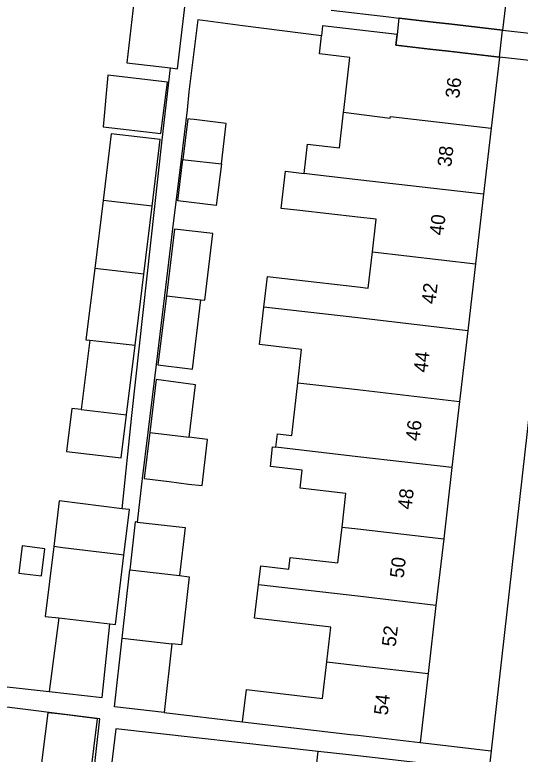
# Model space of a CAD drawing. Extents: x 161696 to 162377, y 380761 to 381673.
# Drawn here: x 161975.5 to 162011.6, y 381041 to 381093.8 of the extents above; entities that cross this region are included whole.
import ezdxf

# ---------------------------------------------------------------- set-up
doc = ezdxf.new("R2010")
doc.units = 0
for name, color, linetype in [('IMGEO_Pand', 7, 'Continuous'), ('IMGEO_Pand_nummerreeks', 7, 'Continuous'), ('IMGEO_Pand_overbouw', 7, 'Continuous'), ('IMGEO_Voetpad_open', 7, 'Continuous')]:
    doc.layers.add(name, color=color, linetype=linetype)

msp = doc.modelspace()

# ---------------------------------------------------------------- linework, layer by layer
at = {"layer": 'IMGEO_Pand'}
for points in [[(162010.992, 381098.263), (162010.343, 381092.663)], [(161984.096, 381095.314), (161983.519, 381090.325), (161986.632, 381089.965)], [(161986.632, 381089.965), (161987.14, 381089.906), (161987.745, 381095.141), (161984.124, 381095.56), (161984.096, 381095.314)], [(161998.101, 381094.083), (162002.22, 381093.605), (162002.942, 381093.521), (162002.961, 381093.519), (162005.377, 381093.239), (162006.726, 381093.082), (162010.343, 381092.663)], [(162010.119, 381090.735), (162006.477, 381091.157), (162005.153, 381091.311), (162002.718, 381091.593), (162002.806, 381092.348), (161997.491, 381092.965), (161997.41, 381092.267)], [(161998.983, 381086.811), (161998.997, 381086.93), (161999.437, 381090.719), (161997.26, 381090.972), (161997.41, 381092.267)], [(162010.119, 381090.735), (162009.531, 381085.664)], [(161985.946, 381085.299), (161986.41, 381088.96), (161982.155, 381089.452), (161981.82, 381085.776), (161985.946, 381085.299)], [(161996.182, 381082.433), (161996.424, 381084.519), (161998.686, 381084.256), (161998.983, 381086.811)], [(161998.983, 381086.811), (162002.315, 381086.376), (162002.329, 381086.499), (162009.531, 381085.664)], [(161990.265, 381083.119), (161990.616, 381086.009), (161988.331, 381086.287), (161988.028, 381086.324), (161987.876, 381086.342), (161987.522, 381083.437)], [(162009.531, 381085.664), (162008.985, 381080.948)], [(161985.322, 381080.096), (161985.906, 381084.854), (161982.4, 381085.259), (161981.816, 381080.502)], [(161990.265, 381083.119), (161989.902, 381080.141), (161987.161, 381080.475), (161987.522, 381083.437)], [(161987.522, 381083.437), (161987.676, 381083.419), (161990.265, 381083.119)], [(162001.043, 381076.835), (162001.314, 381079.187), (162000, 381079.311), (161995.875, 381079.789), (161994.524, 381079.946), (161994.831, 381082.59), (161996.182, 381082.433)], [(162008.985, 381080.948), (162000, 381081.99), (161996.945, 381082.344), (161996.182, 381082.433)], [(162008.985, 381080.948), (162008.409, 381075.981)], [(161981.816, 381080.502), (161981.22, 381075.647)], [(161985.322, 381080.096), (161981.816, 381080.502)], [(161984.728, 381075.257), (161985.322, 381080.096)], [(161988.801, 381073.427), (161989.082, 381073.394), (161989.661, 381078.154), (161986.917, 381078.473), (161986.337, 381073.713)], [(161993.302, 381072.906), (161993.555, 381075.087), (161995.419, 381074.871), (162000, 381074.34), (162000.746, 381074.253), (162001.043, 381076.835)], [(162001.043, 381076.835), (162008.409, 381075.981)], [(161981.22, 381075.647), (161980.596, 381070.56), (161980.873, 381070.529)], [(161984.728, 381075.257), (161981.22, 381075.647)], [(162008.409, 381075.981), (162007.857, 381071.218)], [(161984.104, 381070.174), (161984.728, 381075.257)], [(161986.337, 381073.713), (161985.737, 381068.79), (161988.027, 381068.491), (161988.197, 381068.469), (161988.801, 381073.427)], [(161986.337, 381073.713), (161988.801, 381073.427)], [(161995.72, 381067.506), (161995.995, 381069.879), (161992.992, 381070.227), (161993.302, 381072.906)], [(162007.857, 381071.218), (162000, 381072.129), (161995.166, 381072.69), (161993.302, 381072.906)], [(162007.857, 381071.218), (162007.271, 381066.168)], [(161980.873, 381070.529), (161980.267, 381065.59)], [(161980.873, 381070.529), (161984.104, 381070.174)], [(161983.496, 381065.217), (161984.104, 381070.174)], [(161987.966, 381063.615), (161988.422, 381067.361), (161985.608, 381067.728), (161985.146, 381063.942)], [(161994.163, 381062.898), (161994.273, 381063.848), (161995.283, 381063.731), (161995.72, 381067.506)], [(161995.72, 381067.506), (161999.975, 381067.013), (162007.271, 381066.168)], [(162007.271, 381066.168), (162006.724, 381061.442)], [(161980.267, 381065.59), (161979.588, 381065.668), (161979.212, 381062.605), (161983.12, 381062.154), (161983.496, 381065.217)], [(161980.267, 381065.59), (161983.496, 381065.217)], [(161985.146, 381063.942), (161984.747, 381060.663), (161986.549, 381060.444), (161987.927, 381060.276), (161988.882, 381060.16), (161989.283, 381063.462), (161988.328, 381063.573), (161987.966, 381063.615)], [(161985.146, 381063.942), (161987.966, 381063.615)], [(161998.876, 381057.2), (161999.154, 381059.601), (161995.884, 381059.979), (161996.032, 381061.257), (161993.761, 381061.52), (161993.924, 381062.926), (161994.163, 381062.898)], [(162006.724, 381061.442), (162000, 381062.221), (161994.163, 381062.898)], [(162006.724, 381061.442), (162006.134, 381056.359)], [(161983.174, 381058.514), (161978.694, 381059.064), (161978.295, 381055.807)], [(161983.309, 381055.202), (161983.707, 381058.449), (161983.174, 381058.514)], [(161984.26, 381057.563), (161984.119, 381057.579), (161983.735, 381054.146)], [(161984.26, 381057.563), (161987.669, 381057.182), (161987.283, 381053.735)], [(161992.916, 381053.082), (161993.073, 381054.433), (161995.089, 381054.199), (161995.186, 381055.038), (161998.58, 381054.645), (161998.876, 381057.2)], [(161998.876, 381057.2), (162000, 381057.07), (162006.134, 381056.359)], [(162006.134, 381056.359), (162005.584, 381051.613)], [(161975.81, 381053.922), (161977.42, 381053.725), (161977.656, 381055.657), (161976.047, 381055.854), (161975.81, 381053.922)], [(161978.295, 381055.807), (161977.683, 381050.827), (161978.658, 381050.714)], [(161983.309, 381055.202), (161982.719, 381055.273), (161978.949, 381055.728), (161978.295, 381055.807)], [(161982.31, 381050.292), (161982.7, 381050.247), (161983.309, 381055.202)], [(161983.191, 381049.281), (161983.735, 381054.146)], [(161983.735, 381054.146), (161987.283, 381053.735)], [(161987.283, 381053.735), (161987.968, 381053.655), (161987.423, 381048.79), (161986.722, 381048.869)], [(161997.784, 381047.589), (161998.07, 381050.061), (161992.639, 381050.691), (161992.916, 381053.082)], [(162005.584, 381051.613), (162000, 381052.261), (161992.916, 381053.082)], [(162005.584, 381051.613), (162005.021, 381046.75)], [(161978.658, 381050.714), (161977.976, 381045.458)], [(161977.976, 381045.458), (161981.757, 381045.035), (161982.31, 381050.292)], [(161978.658, 381050.714), (161982.31, 381050.292)], [(161986.174, 381043.974), (161982.641, 381044.369), (161983.191, 381049.281)], [(161983.191, 381049.281), (161986.722, 381048.869)], [(161986.722, 381048.869), (161986.174, 381043.974)], [(161991.781, 381043.296), (161992.049, 381045.6), (161994.264, 381045.343), (161997.48, 381044.97), (161997.784, 381047.589)], [(161997.784, 381047.589), (162000, 381047.332), (162005.021, 381046.75)], [(162005.021, 381046.75), (162004.45, 381041.827)], [(161980.69, 381037.545), (161981.411, 381043.525), (161979.211, 381043.791), (161978.377, 381043.892), (161977.866, 381043.954), (161977.503, 381040.959), (161977.146, 381038.013)], [(161991.781, 381043.296), (161993.997, 381043.039), (161999.484, 381042.404), (162000.001, 381042.343), (162004.45, 381041.827)], [(161993.361, 381035.406), (161993.645, 381037.854), (161994.123, 381037.799), (161994.586, 381037.745), (161996.736, 381037.497), (161997.165, 381041.197)], [(162004.334, 381040.366), (162000, 381040.869), (161999.368, 381040.943), (161997.165, 381041.197)]]:
    msp.add_lwpolyline(points, dxfattribs=at)
at = {"layer": 'IMGEO_Pand_overbouw'}
msp.add_lwpolyline([(162010.343, 381092.663), (162006.726, 381093.082), (162005.377, 381093.239), (162002.961, 381093.519), (162002.942, 381093.521), (162002.806, 381092.348), (162002.718, 381091.593), (162005.153, 381091.311), (162006.477, 381091.157), (162010.119, 381090.735)], close=True, dxfattribs=at)
at = {"layer": 'IMGEO_Voetpad_open'}
for points in [[(161997.41, 381092.267), (161991.792, 381092.98), (161988.59, 381093.391), (161987.931, 381088.252), (161987.811, 381086.967), (161987.384, 381083.453), (161986.779, 381078.489), (161986.2, 381073.729), (161985.601, 381068.808), (161985.01, 381063.958), (161984.611, 381060.68), (161984.26, 381057.563)], [(162010.343, 381092.663), (162015.25, 381092.109)], [(162015.033, 381090.181), (162010.119, 381090.735)], [(161983.174, 381058.514), (161983.874, 381065.173), (161986.04, 381084.838), (161986.632, 381089.965)], [(162015.033, 381090.181), (162009.512, 381041.24)], [(161968.925, 381046.472), (161977.976, 381045.458)], [(161980.281, 381031.865), (161981.587, 381043.512), (161965.235, 381045.562)], [(161986.174, 381043.974), (161991.781, 381043.296)], [(161997.165, 381041.197), (161982.721, 381042.814), (161981.398, 381031.731)], [(162004.45, 381041.827), (162009.512, 381041.24)], [(162009.512, 381041.24), (162009.346, 381039.768)]]:
    msp.add_lwpolyline(points, dxfattribs=at)

# ---------------------------------------------------------------- texts
at = {"layer": 'IMGEO_Pand_nummerreeks'}
for s, p in [('36', (162007.237, 381087.759)), ('38', (162006.671, 381082.871)), ('40', (162006.104, 381077.98)), ('42', (162005.536, 381073.083)), ('44', (162004.969, 381068.195)), ('46', (162004.402, 381063.305)), ('48', (162003.836, 381058.417)), ('50', (162003.27, 381053.526)), ('52', (162002.702, 381048.629)), ('54', (162002.135, 381043.741))]:
    msp.add_text(s, height=1, rotation=83.3883, dxfattribs=at).set_placement(p)

doc.saveas('drawing.dxf')
